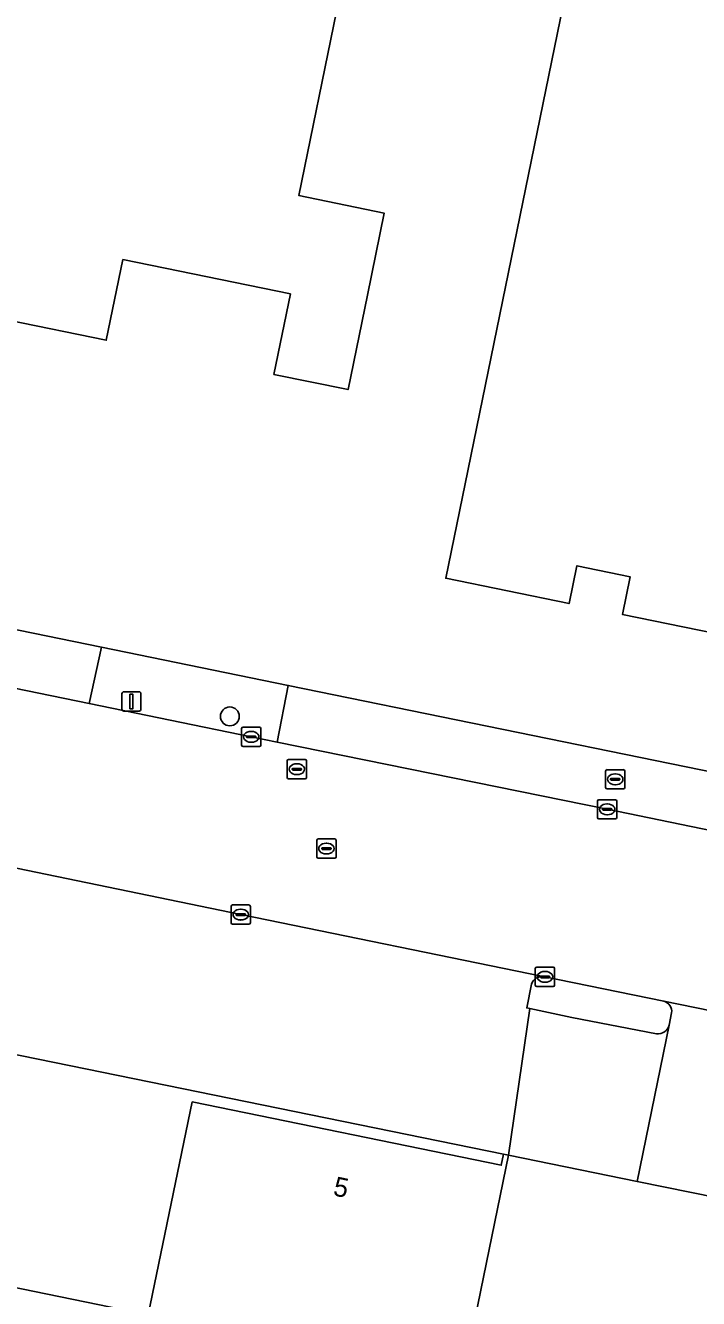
# Model space of a CAD drawing. Extents: x 157692 to 159674, y 381452 to 383291.
# Drawn here: x 158750.1 to 158785, y 382274.1 to 382340.2 of the extents above; entities that cross this region are included whole.
import ezdxf

# ---------------------------------------------------------------- set-up
doc = ezdxf.new("R2010")
doc.units = 0
for name, color, linetype in [('IMGEO_Boom', 7, 'Continuous'), ('IMGEO_Brandkraan', 7, 'Continuous'), ('IMGEO_Erf', 7, 'Continuous'), ('IMGEO_Kolk', 7, 'Continuous'), ('IMGEO_Lichtmast', 7, 'Continuous'), ('IMGEO_Pand', 7, 'Continuous'), ('IMGEO_Pand_nummerreeks', 7, 'Continuous'), ('IMGEO_Parkeervlak_open', 7, 'Continuous'), ('IMGEO_Rijbaan_lokaal_open', 7, 'Continuous'), ('IMGEO_Rioolput', 7, 'Continuous'), ('IMGEO_Voetpad_open', 7, 'Continuous')]:
    doc.layers.add(name, color=color, linetype=linetype)

msp = doc.modelspace()

# ---------------------------------------------------------------- linework, layer by layer
at = {"layer": 'IMGEO_Boom'}
msp.add_circle((158760.714, 382304.334), 0.489, dxfattribs=at)
at = {"layer": 'IMGEO_Brandkraan'}
for p, q in [((158780.209, 382300.643), (158780.209, 382301.495)), ((158780.284, 382301.569), (158781.136, 382301.569)), ((158780.468, 382301.063), (158780.468, 382301.075)), ((158780.906, 382301.026), (158780.508, 382301.026)), ((158780.511, 382301.112), (158780.909, 382301.112)), ((158780.697, 382301.349), (158780.722, 382301.349)), ((158780.952, 382301.075), (158780.952, 382301.063)), ((158781.21, 382301.495), (158781.21, 382300.643)), ((158781.136, 382300.569), (158780.284, 382300.569)), ((158780.72, 382300.789), (158780.695, 382300.789))]:
    msp.add_line(p, q, dxfattribs=at)
for points in [[(158780.209, 382300.643), (158780.209, 382301.495)], [(158780.284, 382301.569), (158781.136, 382301.569)], [(158781.21, 382301.495), (158781.21, 382300.643)], [(158781.136, 382300.569), (158780.284, 382300.569)]]:
    msp.add_lwpolyline(points, dxfattribs=at)
for centre, radius, start, end in [((158780.286, 382301.493), 0.0765, 91.55205, 178.44795), ((158780.286, 382301.493), 0.0765, 91.55205, 178.44795), ((158780.508, 382301.072), 0.0403, 85.87752, 175.75265), ((158780.505, 382301.062), 0.0366, 178.93798, 274.71019), ((158780.909, 382301.069), 0.043, 264.86636, 352.45326), ((158780.913, 382301.074), 0.0386, 1.73085, 96.63898), ((158781.134, 382301.493), 0.0765, 1.55205, 88.44795), ((158781.134, 382301.493), 0.0765, 1.55205, 88.44795), ((158780.286, 382300.645), 0.0765, 181.55205, 268.44795), ((158780.286, 382300.645), 0.0765, 181.55205, 268.44795), ((158781.134, 382300.645), 0.0765, 271.55205, 358.44795), ((158781.134, 382300.645), 0.0765, 271.55205, 358.44795)]:
    msp.add_arc(centre, radius, start, end, dxfattribs=at)
for centre, major_axis, ratio, start_param, end_param in [((158780.696, 382301.069), (-0.387, 0.002), 0.722429, 4.712389, 7.853982), ((158780.721, 382301.069), (-0.39, 0.002), 0.717154, 1.570796, 4.712389)]:
    msp.add_ellipse(centre, major_axis=major_axis, ratio=ratio, start_param=start_param, end_param=end_param, dxfattribs=at)
at = {"layer": 'IMGEO_Erf'}
for points in [[(158824.151, 382357.259), (158815.262, 382313.848), (158814.259, 382308.949), (158798.11, 382312.256), (158796.907, 382306.378), (158781.083, 382309.618), (158781.485, 382311.579), (158778.722, 382312.145), (158778.32, 382310.184), (158771.912, 382311.496), (158772.916, 382316.395), (158781.288, 382357.286)], [(158766.252, 382340.884), (158764.298, 382331.343), (158768.72, 382330.438), (158767.848, 382326.179), (158766.845, 382321.28), (158762.998, 382322.068), (158763.854, 382326.248), (158755.16, 382328.028), (158754.302, 382323.838), (158744.14, 382325.919), (158728.259, 382329.17), (158718.497, 382330.96), (158720.398, 382340.369)], [(158703.868, 382232.929), (158737.91, 382225.935), (158740.836, 382240.44), (158722.149, 382244.289), (158723.325, 382250), (158729.667, 382280.789), (158730.675, 382285.686), (158742.158, 382283.335), (158747.254, 382282.292), (158749.35, 382281.863), (158747.95, 382275.046), (158756.482, 382273.294), (158758.758, 382284.334), (158774.797, 382281.051), (158774.915, 382281.626), (158583.923, 382320.599)], [(158739.897, 382310.815), (158745.516, 382309.667), (158754.049, 382307.922), (158763.74, 382305.941), (158825.695, 382293.283), (158865.561, 382285.172), (158872.186, 382283.72), (158876.329, 382282.962), (158882.131, 382281.773), (158888.158, 382280.537), (158988.039, 382260.114), (159000, 382257.67), (159006.103, 382256.423), (159011.658, 382255.288), (159018.046, 382253.981), (159023.028, 382252.988), (159037.803, 382250), (159039.91, 382249.574), (159043.144, 382248.92), (159043.356, 382248.877), (159043.484, 382248.846), (159053.13, 382246.78), (159055.84, 382246.213), (159072.286, 382242.773)], [(158849.36, 382266.519), (158843.049, 382267.8), (158792.867, 382277.983), (158781.85, 382280.218), (158775.174, 382281.573), (158774.171, 382276.675), (158768.711, 382250), (158768.445, 382248.698), (158762.079, 382250), (158752.1, 382252.041), (158752.766, 382255.271), (158744.243, 382257.017), (158742.801, 382250), (158740.836, 382240.44), (158765.247, 382235.426), (158752.653, 382174.095)]]:
    msp.add_lwpolyline(points, dxfattribs=at)
at = {"layer": 'IMGEO_Kolk'}
for p, q in [((158761.321, 382302.846), (158761.321, 382303.698)), ((158761.396, 382303.772), (158762.248, 382303.772)), ((158762.322, 382303.698), (158762.322, 382302.846)), ((158761.58, 382303.266), (158761.58, 382303.278)), ((158762.018, 382303.229), (158761.62, 382303.229)), ((158761.623, 382303.315), (158762.021, 382303.315)), ((158761.832, 382302.992), (158761.807, 382302.992)), ((158761.809, 382303.552), (158761.834, 382303.552)), ((158762.064, 382303.278), (158762.064, 382303.266)), ((158762.248, 382302.772), (158761.396, 382302.772)), ((158779.792, 382299.086), (158779.792, 382299.938)), ((158779.867, 382300.012), (158780.719, 382300.012)), ((158780.28, 382299.792), (158780.305, 382299.792)), ((158780.793, 382299.938), (158780.793, 382299.086)), ((158780.719, 382299.012), (158779.867, 382299.012)), ((158780.051, 382299.506), (158780.051, 382299.518)), ((158780.489, 382299.469), (158780.091, 382299.469)), ((158780.094, 382299.555), (158780.492, 382299.555)), ((158780.303, 382299.232), (158780.278, 382299.232)), ((158780.535, 382299.518), (158780.535, 382299.506)), ((158760.779, 382293.626), (158760.779, 382294.478)), ((158760.854, 382294.552), (158761.706, 382294.552)), ((158761.78, 382294.478), (158761.78, 382293.626)), ((158761.038, 382294.046), (158761.038, 382294.058)), ((158761.476, 382294.009), (158761.078, 382294.009)), ((158761.081, 382294.095), (158761.479, 382294.095)), ((158761.29, 382293.772), (158761.265, 382293.772)), ((158761.267, 382294.332), (158761.292, 382294.332)), ((158761.522, 382294.058), (158761.522, 382294.046)), ((158761.706, 382293.552), (158760.854, 382293.552)), ((158776.563, 382290.397), (158776.563, 382291.249)), ((158776.638, 382291.323), (158777.49, 382291.323)), ((158777.051, 382291.103), (158777.076, 382291.103)), ((158777.564, 382291.249), (158777.564, 382290.397)), ((158776.822, 382290.817), (158776.822, 382290.829)), ((158777.26, 382290.78), (158776.862, 382290.78)), ((158776.865, 382290.866), (158777.263, 382290.866)), ((158777.074, 382290.543), (158777.049, 382290.543)), ((158777.306, 382290.829), (158777.306, 382290.817)), ((158777.49, 382290.323), (158776.638, 382290.323))]:
    msp.add_line(p, q, dxfattribs=at)
for points in [[(158761.321, 382302.846), (158761.321, 382303.698)], [(158761.396, 382303.772), (158762.248, 382303.772)], [(158762.322, 382303.698), (158762.322, 382302.846)], [(158762.248, 382302.772), (158761.396, 382302.772)], [(158779.792, 382299.086), (158779.792, 382299.938)], [(158779.867, 382300.012), (158780.719, 382300.012)], [(158780.793, 382299.938), (158780.793, 382299.086)], [(158780.719, 382299.012), (158779.867, 382299.012)], [(158760.779, 382293.626), (158760.779, 382294.478)], [(158760.854, 382294.552), (158761.706, 382294.552)], [(158761.78, 382294.478), (158761.78, 382293.626)], [(158761.706, 382293.552), (158760.854, 382293.552)], [(158776.563, 382290.397), (158776.563, 382291.249)], [(158776.638, 382291.323), (158777.49, 382291.323)], [(158777.564, 382291.249), (158777.564, 382290.397)], [(158777.49, 382290.323), (158776.638, 382290.323)]]:
    msp.add_lwpolyline(points, dxfattribs=at)
for centre, radius, start, end in [((158761.398, 382303.696), 0.0765, 91.55205, 178.44795), ((158761.398, 382303.696), 0.0765, 91.55205, 178.44795), ((158762.246, 382303.696), 0.0765, 1.55205, 88.44795), ((158762.246, 382303.696), 0.0765, 1.55205, 88.44795), ((158761.62, 382303.275), 0.0403, 85.87752, 175.75265), ((158761.617, 382303.265), 0.0366, 178.93798, 274.71019), ((158762.021, 382303.272), 0.043, 264.86636, 352.45326), ((158762.025, 382303.277), 0.0386, 1.73085, 96.63898), ((158761.398, 382302.848), 0.0765, 181.55205, 268.44795), ((158761.398, 382302.848), 0.0765, 181.55205, 268.44795), ((158762.246, 382302.848), 0.0765, 271.55205, 358.44795), ((158762.246, 382302.848), 0.0765, 271.55205, 358.44795), ((158779.869, 382299.936), 0.0765, 91.55205, 178.44795), ((158779.869, 382299.936), 0.0765, 91.55205, 178.44795), ((158780.717, 382299.936), 0.0765, 1.55205, 88.44795), ((158780.717, 382299.936), 0.0765, 1.55205, 88.44795), ((158779.869, 382299.088), 0.0765, 181.55205, 268.44795), ((158779.869, 382299.088), 0.0765, 181.55205, 268.44795), ((158780.091, 382299.515), 0.0403, 85.87752, 175.75265), ((158780.088, 382299.505), 0.0366, 178.93798, 274.71019), ((158780.492, 382299.512), 0.043, 264.86636, 352.45326), ((158780.496, 382299.517), 0.0386, 1.73085, 96.63898), ((158780.717, 382299.088), 0.0765, 271.55205, 358.44795), ((158780.717, 382299.088), 0.0765, 271.55205, 358.44795), ((158760.856, 382294.476), 0.0765, 91.55205, 178.44795), ((158760.856, 382294.476), 0.0765, 91.55205, 178.44795), ((158761.704, 382294.476), 0.0765, 1.55205, 88.44795), ((158761.704, 382294.476), 0.0765, 1.55205, 88.44795), ((158761.078, 382294.055), 0.0403, 85.87752, 175.75265), ((158761.075, 382294.045), 0.0366, 178.93798, 274.71019), ((158761.479, 382294.052), 0.043, 264.86636, 352.45326), ((158761.483, 382294.057), 0.0386, 1.73085, 96.63898), ((158760.856, 382293.628), 0.0765, 181.55205, 268.44795), ((158760.856, 382293.628), 0.0765, 181.55205, 268.44795), ((158761.704, 382293.628), 0.0765, 271.55205, 358.44795), ((158761.704, 382293.628), 0.0765, 271.55205, 358.44795), ((158776.64, 382291.247), 0.0765, 91.55205, 178.44795), ((158776.64, 382291.247), 0.0765, 91.55205, 178.44795), ((158777.488, 382291.247), 0.0765, 1.55205, 88.44795), ((158777.488, 382291.247), 0.0765, 1.55205, 88.44795), ((158776.64, 382290.399), 0.0765, 181.55205, 268.44795), ((158776.64, 382290.399), 0.0765, 181.55205, 268.44795), ((158776.862, 382290.826), 0.0403, 85.87752, 175.75265), ((158776.859, 382290.816), 0.0366, 178.93798, 274.71019), ((158777.263, 382290.823), 0.043, 264.86636, 352.45326), ((158777.267, 382290.828), 0.0386, 1.73085, 96.63898), ((158777.488, 382290.399), 0.0765, 271.55205, 358.44795), ((158777.488, 382290.399), 0.0765, 271.55205, 358.44795)]:
    msp.add_arc(centre, radius, start, end, dxfattribs=at)
for centre, major_axis, ratio, start_param, end_param in [((158761.808, 382303.272), (-0.387, 0.002), 0.722429, 4.712389, 7.853982), ((158761.833, 382303.272), (-0.39, 0.002), 0.717154, 1.570796, 4.712389), ((158780.279, 382299.512), (-0.387, 0.002), 0.722429, 4.712389, 7.853982), ((158780.304, 382299.512), (-0.39, 0.002), 0.717154, 1.570796, 4.712389), ((158761.266, 382294.052), (-0.387, 0.002), 0.722429, 4.712389, 7.853982), ((158761.291, 382294.052), (-0.39, 0.002), 0.717154, 1.570796, 4.712389), ((158777.05, 382290.823), (-0.387, 0.002), 0.722429, 4.712389, 7.853982), ((158777.075, 382290.823), (-0.39, 0.002), 0.717154, 1.570796, 4.712389)]:
    msp.add_ellipse(centre, major_axis=major_axis, ratio=ratio, start_param=start_param, end_param=end_param, dxfattribs=at)
at = {"layer": 'IMGEO_Lichtmast'}
for p, q in [((158755.211, 382305.608), (158756.001, 382305.608)), ((158756.001, 382305.608), (158755.211, 382305.608)), ((158755.111, 382304.708), (158755.111, 382305.508)), ((158755.111, 382305.508), (158755.111, 382304.708)), ((158756.101, 382305.508), (158756.101, 382304.708)), ((158756.101, 382304.708), (158756.101, 382305.508)), ((158756.001, 382304.608), (158755.211, 382304.608)), ((158755.211, 382304.608), (158756.001, 382304.608))]:
    msp.add_line(p, q, dxfattribs=at)
msp.add_lwpolyline([(158755.531, 382305.483), (158755.681, 382305.483), (158755.681, 382304.733), (158755.531, 382304.733), (158755.531, 382305.483)], dxfattribs=at)
for centre, start, end in [((158755.211, 382305.508), 90, 180), ((158755.211, 382305.508), 90, 180), ((158756.001, 382305.508), 0, 90), ((158756.001, 382305.508), 360, 90), ((158755.211, 382304.708), 180, 270), ((158755.211, 382304.708), 180, 270), ((158756.001, 382304.708), 270, 0), ((158756.001, 382304.708), 270, 0)]:
    msp.add_arc(centre, 0.1, start, end, dxfattribs=at)
at = {"layer": 'IMGEO_Pand'}
for points in [[(158824.28, 382357.23), (158833.317, 382400.896), (158833.095, 382400.942), (158834.229, 382406.416), (158808.506, 382411.747), (158806.684, 382402.954), (158784.407, 382407.428), (158776.447, 382368.394), (158783.276, 382366.994), (158782.177, 382361.626), (158785.594, 382360.925), (158784.705, 382356.586), (158781.288, 382357.286), (158772.916, 382316.395), (158771.912, 382311.496), (158778.32, 382310.184), (158778.722, 382312.145), (158781.485, 382311.579), (158781.083, 382309.618), (158796.907, 382306.378), (158798.11, 382312.256), (158814.259, 382308.949), (158815.262, 382313.848), (158824.151, 382357.259)], [(158766.252, 382340.884), (158744.215, 382345.401), (158742.265, 382335.888), (158736.753, 382337.018), (158720.398, 382340.369), (158718.497, 382330.96), (158728.259, 382329.17), (158744.14, 382325.919), (158754.302, 382323.838), (158755.16, 382328.028), (158763.854, 382326.248), (158762.998, 382322.068), (158766.845, 382321.28), (158767.848, 382326.179), (158768.72, 382330.438), (158764.298, 382331.343)], [(158747.95, 382275.046), (158744.243, 382257.017), (158752.766, 382255.271), (158752.1, 382252.041), (158762.079, 382250), (158768.445, 382248.698), (158768.711, 382250), (158774.171, 382276.675), (158775.174, 382281.573), (158774.915, 382281.626), (158774.797, 382281.051), (158758.758, 382284.334), (158756.482, 382273.294)]]:
    msp.add_lwpolyline(points, close=True, dxfattribs=at)
at = {"layer": 'IMGEO_Parkeervlak_open'}
msp.add_lwpolyline([(158782.848, 382287.871), (158778.466, 382288.723), (158776.28, 382289.179), (158775.174, 382281.573), (158781.85, 382280.218), (158783.509, 382288.325)], dxfattribs=at)
msp.add_arc((158782.927, 382288.464), 0.598, 262.4043, 346.56122, dxfattribs=at)
at = {"layer": 'IMGEO_Rijbaan_lokaal_open'}
for points in [[(158585.369, 382330.295), (158606.304, 382326.032), (158627.099, 382321.705), (158645.918, 382317.846), (158664.706, 382313.983), (158683.357, 382310.127), (158703.229, 382305.989), (158720.558, 382302.454), (158740.076, 382298.433), (158761.28, 382294.05), (158776.976, 382290.837), (158783.229, 382289.567), (158794.751, 382287.205), (158799.061, 382286.324), (158819.844, 382282.089), (158838.842, 382278.204), (158844.942, 382276.94), (158852.145, 382275.448)], [(158859.681, 382283.22), (158840.554, 382287.183), (158825.094, 382290.327), (158820.213, 382291.319), (158800.497, 382295.362), (158780.293, 382299.514), (158763.168, 382302.997), (158761.821, 382303.271), (158753.419, 382304.996), (158744.89, 382306.754)]]:
    msp.add_lwpolyline(points, dxfattribs=at)
at = {"layer": 'IMGEO_Rioolput'}
for p, q in [((158763.689, 382301.168), (158763.689, 382302.02)), ((158763.764, 382302.094), (158764.616, 382302.094)), ((158763.991, 382301.637), (158764.389, 382301.637)), ((158764.177, 382301.874), (158764.202, 382301.874)), ((158764.69, 382302.02), (158764.69, 382301.168)), ((158764.616, 382301.094), (158763.764, 382301.094)), ((158763.948, 382301.588), (158763.948, 382301.6)), ((158764.386, 382301.551), (158763.988, 382301.551)), ((158764.2, 382301.314), (158764.175, 382301.314)), ((158764.432, 382301.6), (158764.432, 382301.588)), ((158765.225, 382297.05), (158765.225, 382297.902)), ((158765.3, 382297.976), (158766.152, 382297.976)), ((158765.713, 382297.756), (158765.738, 382297.756)), ((158766.226, 382297.902), (158766.226, 382297.05)), ((158765.484, 382297.47), (158765.484, 382297.482)), ((158765.922, 382297.433), (158765.524, 382297.433)), ((158765.527, 382297.519), (158765.925, 382297.519)), ((158765.736, 382297.196), (158765.711, 382297.196)), ((158765.968, 382297.482), (158765.968, 382297.47)), ((158766.152, 382296.976), (158765.3, 382296.976))]:
    msp.add_line(p, q, dxfattribs=at)
for points in [[(158763.689, 382301.168), (158763.689, 382302.02)], [(158763.764, 382302.094), (158764.616, 382302.094)], [(158764.69, 382302.02), (158764.69, 382301.168)], [(158764.616, 382301.094), (158763.764, 382301.094)], [(158765.225, 382297.05), (158765.225, 382297.902)], [(158765.3, 382297.976), (158766.152, 382297.976)], [(158766.226, 382297.902), (158766.226, 382297.05)], [(158766.152, 382296.976), (158765.3, 382296.976)]]:
    msp.add_lwpolyline(points, dxfattribs=at)
for centre, radius, start, end in [((158763.766, 382302.018), 0.0765, 91.55205, 178.44795), ((158763.766, 382302.018), 0.0765, 91.55205, 178.44795), ((158763.988, 382301.597), 0.0403, 85.87752, 175.75265), ((158764.393, 382301.599), 0.0386, 1.73085, 96.63898), ((158764.614, 382302.018), 0.0765, 1.55205, 88.44795), ((158764.614, 382302.018), 0.0765, 1.55205, 88.44795), ((158763.766, 382301.17), 0.0765, 181.55205, 268.44795), ((158763.766, 382301.17), 0.0765, 181.55205, 268.44795), ((158763.985, 382301.587), 0.0366, 178.93798, 274.71019), ((158764.389, 382301.594), 0.043, 264.86636, 352.45326), ((158764.614, 382301.17), 0.0765, 271.55205, 358.44795), ((158764.614, 382301.17), 0.0765, 271.55205, 358.44795), ((158765.302, 382297.9), 0.0765, 91.55205, 178.44795), ((158765.302, 382297.9), 0.0765, 91.55205, 178.44795), ((158766.15, 382297.9), 0.0765, 1.55205, 88.44795), ((158766.15, 382297.9), 0.0765, 1.55205, 88.44795), ((158765.302, 382297.052), 0.0765, 181.55205, 268.44795), ((158765.302, 382297.052), 0.0765, 181.55205, 268.44795), ((158765.524, 382297.479), 0.0403, 85.87752, 175.75265), ((158765.521, 382297.469), 0.0366, 178.93798, 274.71019), ((158765.925, 382297.476), 0.043, 264.86636, 352.45326), ((158765.929, 382297.481), 0.0386, 1.73085, 96.63898), ((158766.15, 382297.052), 0.0765, 271.55205, 358.44795), ((158766.15, 382297.052), 0.0765, 271.55205, 358.44795)]:
    msp.add_arc(centre, radius, start, end, dxfattribs=at)
for centre, major_axis, ratio, start_param, end_param in [((158764.176, 382301.594), (-0.387, 0.002), 0.722429, 4.712389, 7.853982), ((158764.201, 382301.594), (-0.39, 0.002), 0.717154, 1.570796, 4.712389), ((158765.712, 382297.476), (-0.387, 0.002), 0.722429, 4.712389, 7.853982), ((158765.737, 382297.476), (-0.39, 0.002), 0.717154, 1.570796, 4.712389)]:
    msp.add_ellipse(centre, major_axis=major_axis, ratio=ratio, start_param=start_param, end_param=end_param, dxfattribs=at)
at = {"layer": 'IMGEO_Voetpad_open'}
for points in [[(158776.976, 382290.837), (158761.28, 382294.05), (158740.076, 382298.433), (158720.558, 382302.454), (158703.229, 382305.989), (158683.357, 382310.127), (158664.706, 382313.983), (158645.918, 382317.846), (158627.099, 382321.705), (158606.304, 382326.032), (158585.369, 382330.295)], [(158585.636, 382328.823), (158583.923, 382320.599), (158774.915, 382281.626), (158775.174, 382281.573), (158776.28, 382289.179), (158776.115, 382289.213), (158776.367, 382290.437)], [(158776.367, 382290.437), (158776.115, 382289.213), (158776.28, 382289.179), (158778.466, 382288.723), (158782.848, 382287.871)], [(158783.229, 382289.567), (158776.976, 382290.837)], [(158783.638, 382288.95), (158783.509, 382288.325), (158781.85, 382280.218), (158792.867, 382277.983), (158794.751, 382287.205), (158783.229, 382289.567)], [(158783.509, 382288.325), (158783.638, 382288.95)]]:
    msp.add_lwpolyline(points, dxfattribs=at)
for points in [[(158745.516, 382309.667), (158744.89, 382306.754), (158753.419, 382304.996), (158754.049, 382307.922)], [(158763.168, 382302.997), (158763.74, 382305.941), (158754.049, 382307.922), (158753.419, 382304.996), (158761.821, 382303.271)], [(158825.695, 382293.283), (158763.74, 382305.941), (158763.168, 382302.997), (158780.293, 382299.514), (158800.497, 382295.362), (158820.213, 382291.319), (158825.094, 382290.327)]]:
    msp.add_lwpolyline(points, close=True, dxfattribs=at)
for centre, radius, start, end in [((158776.909, 382290.276), 0.565, 83.15014, 163.44484), ((158776.909, 382290.276), 0.565, 83.15014, 163.44484), ((158783.079, 382289.024), 0.564, 352.49826, 74.58133), ((158783.079, 382289.024), 0.564, 352.49826, 74.58133), ((158782.927, 382288.464), 0.598, 262.4043, 346.56122)]:
    msp.add_arc(centre, radius, start, end, dxfattribs=at)

# ---------------------------------------------------------------- texts
at = {"layer": 'IMGEO_Pand_nummerreeks'}
msp.add_text('5', height=1, rotation=348.43246, dxfattribs=at).set_placement((158766.028, 382279.498))

doc.saveas('drawing.dxf')
